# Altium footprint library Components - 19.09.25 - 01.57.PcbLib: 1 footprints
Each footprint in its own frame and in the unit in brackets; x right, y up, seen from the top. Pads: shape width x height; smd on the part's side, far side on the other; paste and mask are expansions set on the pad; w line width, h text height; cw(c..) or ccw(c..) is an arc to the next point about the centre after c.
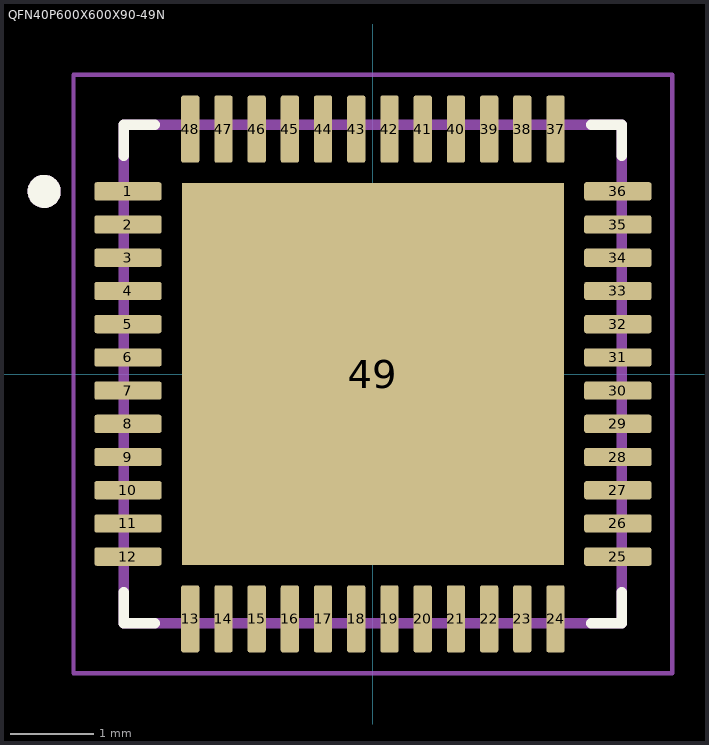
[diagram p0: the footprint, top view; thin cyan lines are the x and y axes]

## QFN40P600X600X90-49N [mm]
height 0.9
pads (49):
  rrect25% 0.81x0.22 smd: 1(-2.95,2.2) 2(-2.95,1.8) 3(-2.95,1.4) 4(-2.95,1) 5(-2.95,0.6) 6(-2.95,0.2) 7(-2.95,-0.2) 8(-2.95,-0.6) 9(-2.95,-1) 10(-2.95,-1.4) 11(-2.95,-1.8) 12(-2.95,-2.2) 25(2.95,-2.2) 26(2.95,-1.8) 27(2.95,-1.4) 28(2.95,-1) 29(2.95,-0.6) 30(2.95,-0.2) 31(2.95,0.2) 32(2.95,0.6) 33(2.95,1) 34(2.95,1.4) 35(2.95,1.8) 36(2.95,2.2)
  rrect25% 0.22x0.81 smd: 13(-2.2,-2.95) 14(-1.8,-2.95) 15(-1.4,-2.95) 16(-1,-2.95) 17(-0.6,-2.95) 18(-0.2,-2.95) 19(0.2,-2.95) 20(0.6,-2.95) 21(1,-2.95) 22(1.4,-2.95) 23(1.8,-2.95) 24(2.2,-2.95) 37(2.2,2.95) 38(1.8,2.95) 39(1.4,2.95) 40(1,2.95) 41(0.6,2.95) 42(0.2,2.95) 43(-0.2,2.95) 44(-0.6,2.95) 45(-1,2.95) 46(-1.4,2.95) 47(-1.8,2.95) 48(-2.2,2.95)
  rect 4.6x4.6 smd paste-3: 49(0,0)
Top Overlay:
  circle w0.2: c-3.96,2.2 r0.1
  lines w0.127: -3,-2.63 -3,-3 -2.63,-3 ; -3,2.63 -3,3 -2.63,3 ; 2.63,-3 3,-3 3,-2.63 ; 2.63,3 3,3 3,2.63
Top Paste:
  region: -0.42,0.42 -1.88,0.42 -1.88,1.88 -0.42,1.88
  region: 1.88,0.42 0.42,0.42 0.42,1.88 1.88,1.88
  region: -0.42,-1.88 -1.88,-1.88 -1.88,-0.42 -0.42,-0.42
  region: 1.88,-1.88 0.42,-1.88 0.42,-0.42 1.88,-0.42
Assembly Top:
  circle w0.2: c-3.96,2.2 r0.1
  lines w0.127: -3,-3 3,-3 3,3 -3,3 -3,-3
Courtyard Top:
  lines w0.05: -3.605,-3.605 3.605,-3.605 3.605,3.605 -3.605,3.605 -3.605,-3.605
